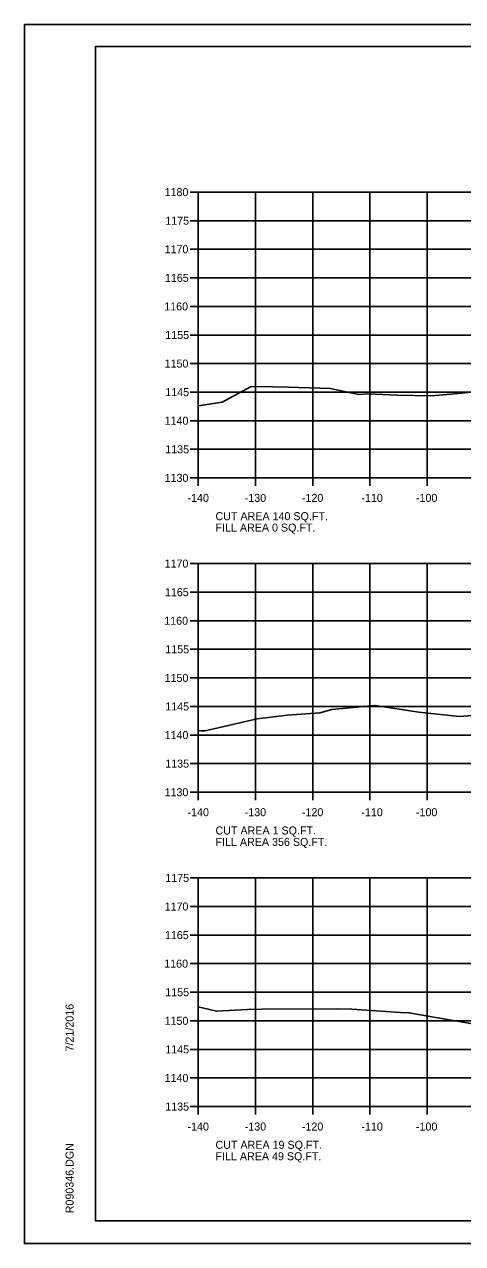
# Model space of a CAD drawing. Extents: x 1368971 to 1374497, y 378717 to 381839.
# Drawn here: x 1369472.5 to 1369549.1, y 378861.8 to 379075.2 of the extents above; entities that cross this region are included whole.
import ezdxf

# ---------------------------------------------------------------- set-up
doc = ezdxf.new("R2010")
doc.units = 0
for name, color, linetype in [('R_Axis', 7, 'Continuous'), ('R_Axis Annot', 7, 'Continuous'), ('R_Border', 7, 'Continuous'), ('R_Exist Surface', 7, 'Continuous'), ('R_Grid', 7, 'Continuous'), ('R_No Plot', 7, 'Continuous')]:
    doc.layers.add(name, color=color, linetype=linetype)

msp = doc.modelspace()

# ---------------------------------------------------------------- linework, layer by layer
at = {"layer": 'R_Axis'}
for p, q in [((1369501.53, 379045.81), (1369502.93, 379045.81)), ((1369502.93, 378995.81), (1369502.93, 379045.81)), ((1369501.53, 379040.81), (1369502.93, 379040.81)), ((1369501.53, 379035.81), (1369502.93, 379035.81)), ((1369501.53, 379030.81), (1369502.93, 379030.81)), ((1369501.53, 379025.81), (1369502.93, 379025.81)), ((1369501.53, 379020.81), (1369502.93, 379020.81)), ((1369501.53, 379015.81), (1369502.93, 379015.81)), ((1369501.53, 379010.81), (1369502.93, 379010.81)), ((1369501.53, 379005.81), (1369502.93, 379005.81)), ((1369501.53, 379000.81), (1369502.93, 379000.81)), ((1369501.53, 378995.81), (1369502.93, 378995.81)), ((1369502.93, 378995.81), (1369782.93, 378995.81)), ((1369502.93, 378994.41), (1369502.93, 378995.81)), ((1369512.93, 378994.41), (1369512.93, 378995.81)), ((1369522.93, 378994.41), (1369522.93, 378995.81)), ((1369532.93, 378994.41), (1369532.93, 378995.81)), ((1369542.93, 378994.41), (1369542.93, 378995.81)), ((1369501.53, 378980.81), (1369502.93, 378980.81)), ((1369502.93, 378940.81), (1369502.93, 378980.81)), ((1369501.53, 378975.81), (1369502.93, 378975.81)), ((1369501.53, 378970.81), (1369502.93, 378970.81)), ((1369501.53, 378965.81), (1369502.93, 378965.81)), ((1369501.53, 378960.81), (1369502.93, 378960.81)), ((1369501.53, 378955.81), (1369502.93, 378955.81)), ((1369501.53, 378950.81), (1369502.93, 378950.81)), ((1369501.53, 378945.81), (1369502.93, 378945.81)), ((1369501.53, 378940.81), (1369502.93, 378940.81)), ((1369502.93, 378940.81), (1369782.93, 378940.81)), ((1369502.93, 378939.41), (1369502.93, 378940.81)), ((1369512.93, 378939.41), (1369512.93, 378940.81)), ((1369522.93, 378939.41), (1369522.93, 378940.81)), ((1369532.93, 378939.41), (1369532.93, 378940.81)), ((1369542.93, 378939.41), (1369542.93, 378940.81)), ((1369501.53, 378925.81), (1369502.93, 378925.81)), ((1369502.93, 378885.81), (1369502.93, 378925.81)), ((1369501.53, 378920.81), (1369502.93, 378920.81)), ((1369501.53, 378915.81), (1369502.93, 378915.81)), ((1369501.53, 378910.81), (1369502.93, 378910.81)), ((1369501.53, 378905.81), (1369502.93, 378905.81)), ((1369501.53, 378900.81), (1369502.93, 378900.81)), ((1369501.53, 378895.81), (1369502.93, 378895.81)), ((1369501.53, 378890.81), (1369502.93, 378890.81)), ((1369501.53, 378885.81), (1369502.93, 378885.81)), ((1369502.93, 378885.81), (1369782.93, 378885.81)), ((1369502.93, 378884.41), (1369502.93, 378885.81)), ((1369512.93, 378884.41), (1369512.93, 378885.81)), ((1369522.93, 378884.41), (1369522.93, 378885.81)), ((1369532.93, 378884.41), (1369532.93, 378885.81)), ((1369542.93, 378884.41), (1369542.93, 378885.81))]:
    msp.add_line(p, q, dxfattribs=at)
at = {"layer": 'R_Border'}
for p, q in [((1369484.93, 379071.27), (1369801.11, 379071.27)), ((1369484.93, 378865.81), (1369484.93, 379071.27)), ((1369484.93, 378865.81), (1369484.93, 378865.81)), ((1369801.11, 378865.81), (1369484.93, 378865.81))]:
    msp.add_line(p, q, dxfattribs=at)
at = {"layer": 'R_Exist Surface'}
for points in [[(1369502.93, 379008.44), (1369507.12, 379009.07), (1369512.05, 379011.76), (1369513.21, 379011.8), (1369518.68, 379011.69), (1369525.97, 379011.47), (1369530.97, 379010.38), (1369532.56, 379010.51), (1369537.67, 379010.28), (1369543.61, 379010.15), (1369547.13, 379010.43), (1369551.36, 379010.88)], [(1369502.93, 378951.58), (1369503.41, 378951.57), (1369504.15, 378951.55), (1369513.23, 378953.62), (1369518.48, 378954.3), (1369524.19, 378954.69), (1369526.27, 378955.3), (1369533.76, 378956.01), (1369533.83, 378956.01), (1369541.46, 378954.84), (1369548.56, 378954.05), (1369558.84, 378954.81)], [(1369502.93, 378903.28), (1369506.12, 378902.51), (1369511.51, 378902.81), (1369514, 378902.85), (1369527.2, 378902.9), (1369529.76, 378902.83), (1369538.26, 378902.26), (1369539.76, 378902.21), (1369557.26, 378899.16)]]:
    msp.add_lwpolyline(points, dxfattribs=at)
at = {"layer": 'R_Grid'}
for p, q in [((1369502.93, 379045.81), (1369782.93, 379045.81)), ((1369502.93, 378995.81), (1369502.93, 379045.81)), ((1369512.93, 378995.81), (1369512.93, 379045.81)), ((1369522.93, 378995.81), (1369522.93, 379045.81)), ((1369532.93, 378995.81), (1369532.93, 379045.81)), ((1369542.93, 378995.81), (1369542.93, 379045.81)), ((1369502.93, 379040.81), (1369782.93, 379040.81)), ((1369502.93, 379035.81), (1369782.93, 379035.81)), ((1369502.93, 379030.81), (1369782.93, 379030.81)), ((1369502.93, 379025.81), (1369782.93, 379025.81)), ((1369502.93, 379020.81), (1369782.93, 379020.81)), ((1369502.93, 379015.81), (1369782.93, 379015.81)), ((1369502.93, 379010.81), (1369782.93, 379010.81)), ((1369502.93, 379005.81), (1369782.93, 379005.81)), ((1369502.93, 379000.81), (1369782.93, 379000.81)), ((1369502.93, 378995.81), (1369782.93, 378995.81)), ((1369502.93, 378980.81), (1369782.93, 378980.81)), ((1369502.93, 378940.81), (1369502.93, 378980.81)), ((1369512.93, 378940.81), (1369512.93, 378980.81)), ((1369522.93, 378940.81), (1369522.93, 378980.81)), ((1369532.93, 378940.81), (1369532.93, 378980.81)), ((1369542.93, 378940.81), (1369542.93, 378980.81)), ((1369502.93, 378975.81), (1369782.93, 378975.81)), ((1369502.93, 378970.81), (1369782.93, 378970.81)), ((1369502.93, 378965.81), (1369782.93, 378965.81)), ((1369502.93, 378960.81), (1369782.93, 378960.81)), ((1369502.93, 378955.81), (1369782.93, 378955.81)), ((1369502.93, 378950.81), (1369782.93, 378950.81)), ((1369502.93, 378945.81), (1369782.93, 378945.81)), ((1369502.93, 378940.81), (1369782.93, 378940.81)), ((1369502.93, 378925.81), (1369782.93, 378925.81)), ((1369502.93, 378885.81), (1369502.93, 378925.81)), ((1369512.93, 378885.81), (1369512.93, 378925.81)), ((1369522.93, 378885.81), (1369522.93, 378925.81)), ((1369532.93, 378885.81), (1369532.93, 378925.81)), ((1369542.93, 378885.81), (1369542.93, 378925.81)), ((1369502.93, 378920.81), (1369782.93, 378920.81)), ((1369502.93, 378915.81), (1369782.93, 378915.81)), ((1369502.93, 378910.81), (1369782.93, 378910.81)), ((1369502.93, 378905.81), (1369782.93, 378905.81)), ((1369502.93, 378900.81), (1369782.93, 378900.81)), ((1369502.93, 378895.81), (1369782.93, 378895.81)), ((1369502.93, 378890.81), (1369782.93, 378890.81)), ((1369502.93, 378885.81), (1369782.93, 378885.81))]:
    msp.add_line(p, q, dxfattribs=at)
at = {"layer": 'R_No Plot'}
for p, q in [((1369472.53, 379075.16), (1369805.86, 379075.16)), ((1369472.53, 378861.83), (1369805.86, 378861.83))]:
    msp.add_line(p, q, dxfattribs=at)
for points in [[(1369472.52, 379075.16), (1369805.86, 379075.16), (1369805.86, 378861.82), (1369472.52, 378861.82)], [(1369718.85, 379071.27), (1369718.85, 379061.39), (1369754.58, 379061.39), (1369754.58, 379058.47), (1369777.78, 379058.47), (1369777.78, 379035.25), (1369801.11, 379035.25), (1369801.11, 378865.81), (1369484.93, 378865.81), (1369484.93, 379071.27)]]:
    msp.add_lwpolyline(points, close=True, dxfattribs=at)

# ---------------------------------------------------------------- texts
at = {"layer": 'R_Axis'}
for p in [(1369502.93, 378995.81), (1369502.93, 378940.81), (1369502.93, 378885.81)]:
    msp.add_text('-', height=0.0001, dxfattribs=at).set_placement(p)
at = {"layer": 'R_Axis Annot'}
for s, p in [('1180', (1369497.03, 379045.11)), ('1175', (1369497.15, 379040.11)), ('1170', (1369497.03, 379035.11)), ('1165', (1369497.09, 379030.11)), ('1160', (1369496.97, 379025.11)), ('1155', (1369497.15, 379020.11)), ('1150', (1369497.03, 379015.11)), ('1145', (1369497.15, 379010.11)), ('1140', (1369497.03, 379005.11)), ('1135', (1369497.15, 379000.11)), ('1130', (1369497.03, 378995.11)), ('-140', (1369501.04, 378991.61)), ('-130', (1369511.04, 378991.61)), ('-120', (1369521.04, 378991.61)), ('-110', (1369531.44, 378991.61)), ('-100', (1369540.98, 378991.61)), ('CUT AREA 140 SQ.FT.', (1369505.93, 378988.41)), ('FILL AREA 0 SQ.FT.', (1369505.93, 378986.41)), ('1170', (1369497.03, 378980.11)), ('1165', (1369497.09, 378975.11)), ('1160', (1369496.97, 378970.11)), ('1155', (1369497.15, 378965.11)), ('1150', (1369497.03, 378960.11)), ('1145', (1369497.15, 378955.11)), ('1140', (1369497.03, 378950.11)), ('1135', (1369497.15, 378945.11)), ('1130', (1369497.03, 378940.11)), ('-140', (1369501.04, 378936.61)), ('-130', (1369511.04, 378936.61)), ('-120', (1369521.04, 378936.61)), ('-110', (1369531.44, 378936.61)), ('-100', (1369540.98, 378936.61)), ('CUT AREA 1 SQ.FT.', (1369505.93, 378933.41)), ('FILL AREA 356 SQ.FT.', (1369505.93, 378931.41)), ('1175', (1369497.15, 378925.11)), ('1170', (1369497.03, 378920.11)), ('1165', (1369497.09, 378915.11)), ('1160', (1369496.97, 378910.11)), ('1155', (1369497.15, 378905.11)), ('1150', (1369497.03, 378900.11)), ('1145', (1369497.15, 378895.11)), ('1140', (1369497.03, 378890.11)), ('1135', (1369497.15, 378885.11)), ('-140', (1369501.04, 378881.61)), ('-130', (1369511.04, 378881.61)), ('-120', (1369521.04, 378881.61)), ('-110', (1369531.44, 378881.61)), ('-100', (1369540.98, 378881.61)), ('CUT AREA 19 SQ.FT.', (1369505.93, 378878.41)), ('FILL AREA 49 SQ.FT.', (1369505.93, 378876.41))]:
    msp.add_text(s, height=1.4, dxfattribs=at).set_placement(p)
at = {"layer": 'R_Border'}
for s, p in [('7/21/2016', (1369481.12, 378895.45)), ('R090346.DGN', (1369481.12, 378867.13))]:
    msp.add_text(s, height=1.4, rotation=90, dxfattribs=at).set_placement(p)

doc.saveas('drawing.dxf')
